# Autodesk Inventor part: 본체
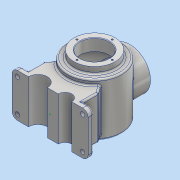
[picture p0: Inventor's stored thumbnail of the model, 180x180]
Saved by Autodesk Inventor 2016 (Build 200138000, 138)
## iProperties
Created: 2018-08
Part Number: 본체
Material: 알루미늄 6061
Document SubType Name: Modeling
Designer: 605-08
Density: 2.7 g/cm^3
Appearance: 알루미늄 - 평지
Mass: 1878.27 g
Surface Area: 1089.41 cm^2
Volume: 695.654 cm^3
Author: 605-08
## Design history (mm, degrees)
sketch "스케치1"
  geometry: 1 further point
sketch "스케치2"
  geometry: L1 (-70, 40)-(70, 40); L2 (70, 40)-(70, -40); L3 (70, -40)-(-70, -40); L4 (-70, -40)-(-70, 40); L5 (-70, 40)-(70, -40); L6 (70, 40)-(-70, -40); 1 further point
  constraints: 12 end point, 2 midpoint, 2 parallel, 1 horizontal, 1 perpendicular
  dimensions: "d0" = 140 distance of L2.end L3.end; "d1" = 80 distance of L1.end L2.end
extrude "돌출1" new body sketch "스케치2" distance "d2" = 10; taper "d3" = 0 deg
sketch "스케치5"
  geometry: L1 (-70, 0)-(-70, 10) reference; L2 (-50, 38.563)-(0, 109.97); L3 (-70, 10)-(70, 10) reference; L4 (-50, 10)-(50, 10); L5 (70, 0)-(-70, 0) reference; L6 (-50, 10)-(-50, 38.563); L7 (0, 10)-(0, 109.97); L8 (50, 10)-(50, 38.563); L9 (50, 38.563)-(0, 109.97); 3 further points
  constraints: 12 end point, 3 midpoint, 1 coincident, 1 horizontal, 1 perpendicular, 1 symmetric about line, 1 vertical, 1 vertical alignment
  dimensions: "d11" = 55 deg angle of L3 L2; "d12" = 100 distance of L4.start L4.end; "d13" = 99.97036 distance of point (0, 10) L2.end
extrude "돌출2" join sketch "스케치5" stored distance "d14" = 80; taper "d15" = 0 deg
sketch "스케치7"
  geometry: 1 further point
sketch "스케치8"
  geometry: C1 r 50 at (0, 82); 1 further point
  constraints: 1 centre point, 1 vertical alignment
  dimensions: "d24" = 100 diameter of C1; "d25" = 82 distance of C1.centre point (0, 0)
extrude "돌출3" join sketch "스케치8" distance "d26" = 50; taper "d28" = 0 deg; dims "d27" = 58, "d29" = 0
sketch "스케치9"
  geometry: L1 (32, -58)-(132, -58) reference; L2 (82, 58)-(82, -58); L3 (132, -58)-(132, 50) reference; L4 (32, -58)-(32, 50) reference; L5 (132, -46.671)-(132, -58); L6 (132, -58)-(82, -58); A1 r 116 centre (82, 58) between (82, -58) and (132, -46.671); 1 further point
  constraints: 6 end point, 2 collinear, 2 point on circle, 1 centre point, 1 midpoint, 1 point on line, 1 vertical, 1 vertical alignment
  dimensions: "d30" = 116 radius of A1
revolve "회전1" sketch "스케치9" stored, may be unused: angle "d34" = 90 deg
sketch "스케치10"
  geometry: C1 r 38 at (0, 0); 1 further point
  constraints: 1 centre point, 1 vertical alignment
  dimensions: "d35" = 76 diameter of C1; "d36" = 82 distance of point (0, -82) C1.centre
extrude "돌출4" join sketch "스케치10" distance "d37" = 12; taper "d38" = 0 deg
node "작업 평면1"
sketch "스케치11"
  geometry: L1 (50, 50)-(-50, 50) reference; C1 r 38 at (0, 0); 1 further point
  constraints: 1 centre point, 1 coincident
  dimensions: "d40" = 76 diameter of C1; "d41" = 50 distance from line of L1 C1.centre
extrude "돌출5" join sketch "스케치11" stored distance "d42" = 12; taper "d43" = 0 deg; dims "d40" = 76, "d41" = 50
sketch "스케치12"
  geometry: 2 further points
  constraints: 1 vertical alignment
  dimensions: "d44" = 82 distance of point (0, -82) point (0, 0)
hole "구멍1" sketch "스케치12" at (0, 0) diameter "d45" = 54; stored, may be unused: countersink angle "d49" = 90 deg, drill point angle "d51" = 0 deg; dims "d46" = 6, "d47" = 4, "d48" = 2, "d50" = 22
sketch "스케치13"
  geometry: L1 (109, 40)-(55, 40) reference; L2 (82, 40)-(122, 40); L3 (122, 40)-(122, -40.163); L4 (82, 40)-(82, -48); A1 r 116 centre (82, 58) between (32, -46.671) and (132, -46.671) reference; A2 r 106 centre (82, 58) between (82, -48) and (122, -40.163); 1 further point
  constraints: 6 end point, 2 point on circle, 1 centre point, 1 collinear, 1 midpoint, 1 perpendicular, 1 vertical
  dimensions: "d52" = 10 radial gap between concentric circles of A1 A2; "d53" = 40 distance of L2.start L2.end
revolve "회전2" sketch "스케치13" stored, may be unused: angle "d54" = 90 deg
sketch "스케치14"
  geometry: 2 further points
  constraints: 1 coincident
hole "구멍2" sketch "스케치14" at (0, 0) diameter "d55" = 54; stored, may be unused: countersink angle "d59" = 90 deg, drill point angle "d61" = 0 deg; dims "d56" = 6, "d57" = 4, "d58" = 2, "d60" = 50
sketch "스케치15"
  geometry: L1 (140, 0)-(0, 0) reference; C1 r 17.5 at (47.5, 0); C2 r 12.5 at (97.5, 0); 3 further points
  constraints: 2 centre point, 2 horizontal alignment, 2 midpoint
  dimensions: "d62" = 35 diameter of C1; "d63" = 25 diameter of C2; "d64" = 22.5 distance of C1.centre point (70, 0); "d65" = 27.5 distance of C2.centre point (70, 0)
extrude "돌출6" cut sketch "스케치15" stored distance "d66" = 12; taper "d67" = 0 deg
node "작업 평면2"
chamfer "모따기1" distance "d71" = 1; stored, may be unused: second distance "d72" = 2, angle "d73" = 45 deg
fillet "모깎기1" dims "d74" = 10
sketch "스케치17"
  geometry: A1 r 10 centre (-60, 30) between (-60, 40) and (-70, 30) reference; 2 further points
  constraints: 1 coincident
hole "구멍3" sketch "스케치17" at (-60, 30) diameter "d75" = 8; stored, may be unused: countersink angle "d79" = 90 deg, drill point angle "d81" = 0 deg; dims "d76" = 6, "d77" = 4, "d78" = 2, "d80" = 50
sketch "스케치18"
  geometry: A1 r 10 centre (-60, -30) between (-70, -30) and (-60, -40) reference; A2 r 10 centre (60, -30) between (60, -40) and (70, -30) reference; A3 r 10 centre (60, 30) between (70, 30) and (60, 40) reference; 4 further points
  constraints: 3 coincident
hole "구멍4" sketch "스케치18" at (-60, -30), (60, -30), (60, 30) diameter "d82" = 8; stored, may be unused: countersink angle "d86" = 90 deg, drill point angle "d88" = 0 deg; dims "d83" = 6, "d84" = 4, "d85" = 2, "d87" = 50
fillet "모깎기2" dims "d89" = 3
fillet "모깎기3" dims "d90" = 3
fillet "모깎기4" dims "d91" = 3
sketch "스케치19"
  geometry: C1 r 28 at (0, 0) reference; 2 further points
  constraints: 1 vertical alignment
  dimensions: "d92" = 32.5 distance of point (0, 32.5) C1.centre
hole "구멍5" sketch "스케치19" at (0, 32.5) diameter "d93" = 3.242; stored, may be unused: countersink angle "d97" = 90 deg, drill point angle "d99" = 118 deg; dims "d94" = 8, "d95" = 4, "d96" = 2, "d98" = 10
sketch "스케치20"
  geometry: 2 further points
  constraints: 1 vertical alignment
  dimensions: "d103" = 32.5 distance of point (0, 32.5) point (0, 0)
hole "구멍6" sketch "스케치20" at (0, 32.5) diameter "d104" = 3.242; stored, may be unused: countersink angle "d108" = 90 deg, drill point angle "d110" = 118 deg; dims "d105" = 8, "d106" = 4, "d107" = 2, "d109" = 10
fillet "모깎기5" dims "d114" = 3
fillet "모깎기6" dims "d115" = 3
node "작업 평면4"
sketch "스케치23"
  geometry: C1 r 32.5 at (0, 0); 1 further point
  constraints: 1 centre point, 1 vertical alignment, 1 other
  dimensions: "d119" = 65 diameter of C1; "d120" = 82 distance of point (0, -82) C1.centre
feature "엠보싱1" sketch "스케치23" dims "d121" = 0.5, "d122" = 0
fillet "모깎기8" dims "d124" = 3
node "솔리드1"
pattern_circular "원형 패턴1" dims angle "d101" = 360 deg
pattern_circular "원형 패턴2" dims angle "d112" = 360 deg
other parameters: "d39" = 147
